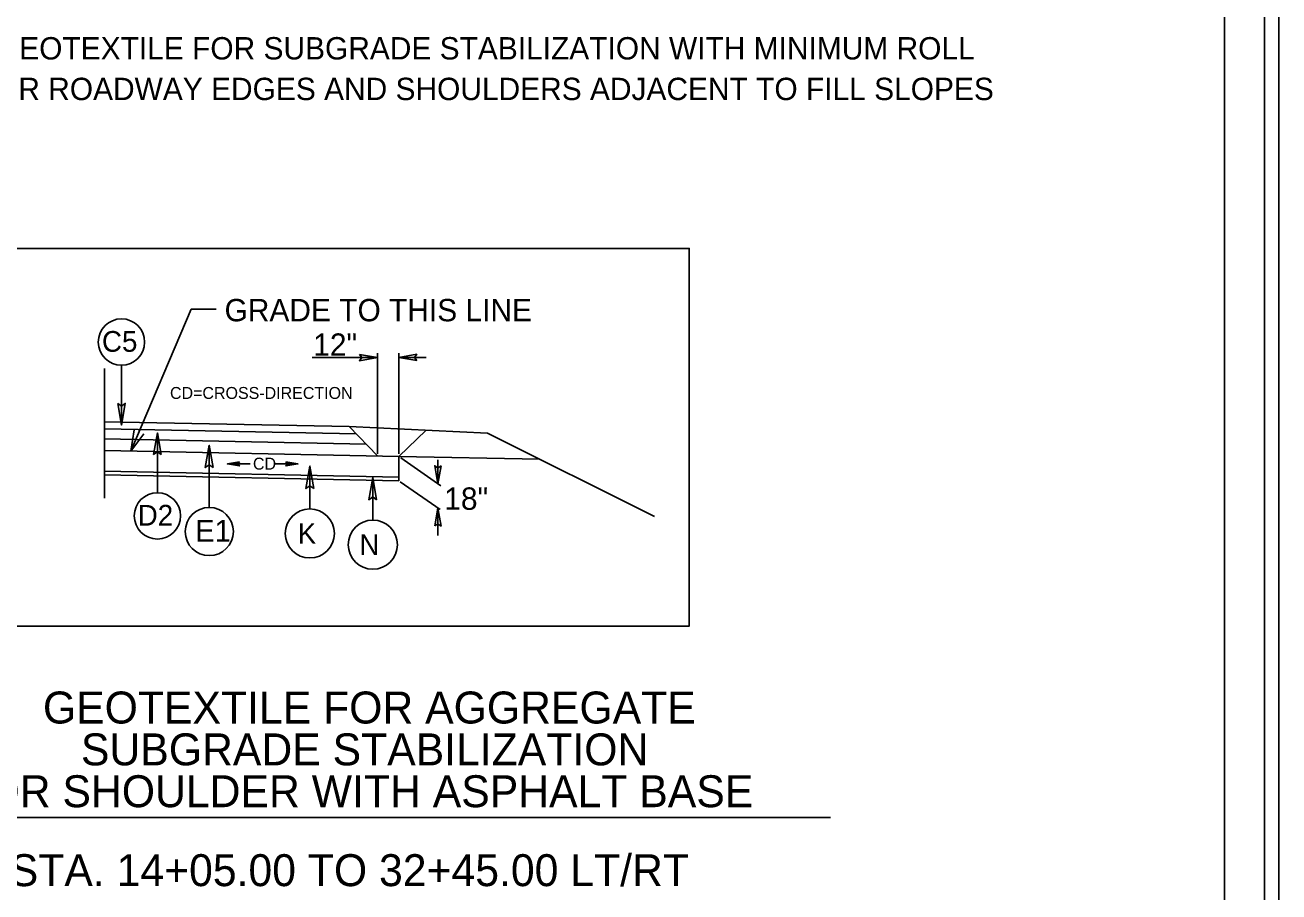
# Model space of a CAD drawing. Extents: x 1901718 to 1902220, y 193828 to 194187.
# Drawn here: x 1902095 to 1902134.24, y 194075.18 to 194102.32 of the extents above; entities that cross this region are included whole.
import ezdxf

# ---------------------------------------------------------------- set-up
doc = ezdxf.new("R2010")
doc.units = 0
for name, color, linetype in [('Old_Level_1', 7, 'Continuous'), ('Old_Level_11', 7, 'Continuous'), ('Old_Level_20', 7, 'Continuous'), ('Prop Dimension', 7, 'Continuous'), ('Prop Dimension Text', 7, 'Continuous'), ('Prop Lane Arrow CELL', 7, 'Continuous'), ('Prop Terminator CELL', 7, 'Continuous'), ('Sheet Border Standard 30in CELL', 7, 'Continuous'), ('Sheet Plot Border Inside CELL', 7, 'Continuous'), ('Sheet Plot Border Outside CELL', 7, 'Continuous'), ('Typical Hinge Slope Interstate CELL', 7, 'Continuous'), ('Typical ID Circle CELL', 7, 'Continuous'), ('Typical Pavement Slope CELL', 7, 'Continuous'), ('Typical Shoulder Slope CELL', 7, 'Continuous'), ('Typical Text General CELL', 7, 'Continuous'), ('Typical Text ID Circle CELL', 7, 'Continuous')]:
    doc.layers.add(name, color=color, linetype=linetype)

msp = doc.modelspace()

# ---------------------------------------------------------------- linework, layer by layer
at = {"layer": 'Old_Level_1'}
msp.add_lwpolyline([(1902098.718, 194089.524), (1902098.312, 194088.983), (1902098.415, 194089.651)], dxfattribs=at)
at = {"layer": 'Old_Level_11'}
for p, q in [((1902098.017, 194091.673), (1902098.017, 194089.799)), ((1902099.14, 194087.677), (1902099.14, 194089.552)), ((1902100.765, 194087.218), (1902100.765, 194089.167)), ((1902100.765, 194087.218), (1902100.765, 194089.167)), ((1902092.269, 194077.506), (1902120.212, 194077.506))]:
    msp.add_line(p, q, dxfattribs=at)
for points in [[(1902094.49, 194095.33), (1902115.785, 194095.33), (1902115.785, 194083.502), (1902094.49, 194083.502)], [(1902097.902, 194090.471), (1902098.017, 194089.799), (1902098.137, 194090.474), (1902098.017, 194090.388)], [(1902099.255, 194088.88), (1902099.14, 194089.552), (1902099.02, 194088.876), (1902099.14, 194088.962)], [(1902100.885, 194088.468), (1902100.765, 194089.167), (1902100.641, 194088.465), (1902100.765, 194088.554)], [(1902104.033, 194087.814), (1902103.913, 194088.512), (1902103.789, 194087.81), (1902103.913, 194087.899)], [(1902106.002, 194087.46), (1902105.882, 194088.158), (1902105.758, 194087.456), (1902105.882, 194087.545)]]:
    msp.add_lwpolyline(points, close=True, dxfattribs=at)
for centre, radius in [((1902098.017, 194092.398), 0.725), ((1902099.14, 194086.952), 0.725), ((1902100.765, 194086.463), 0.754), ((1902100.765, 194086.463), 0.754)]:
    msp.add_circle(centre, radius, dxfattribs=at)
at = {"layer": 'Prop Dimension'}
for p, q in [((1902100.197, 194093.429), (1902098.312, 194088.983)), ((1902100.197, 194093.429), (1902100.985, 194093.429)), ((1902097.484, 194087.511), (1902097.484, 194091.57)), ((1902102.042, 194088.583), (1902101.331, 194088.583)), ((1902102.829, 194088.583), (1902103.539, 194088.583))]:
    msp.add_line(p, q, dxfattribs=at)
at = {"layer": 'Prop Dimension Text'}
for p, q in [((1902103.983, 194091.911), (1902106.03, 194091.911)), ((1902106.03, 194088.894), (1902106.03, 194092.045)), ((1902106.696, 194088.894), (1902106.696, 194092.045)), ((1902106.696, 194091.911), (1902107.554, 194091.911)), ((1902106.758, 194088.771), (1902108.01, 194087.895)), ((1902107.921, 194087.957), (1902107.921, 194088.711)), ((1902106.743, 194088.022), (1902107.991, 194087.148)), ((1902107.919, 194086.343), (1902107.919, 194087.198))]:
    msp.add_line(p, q, dxfattribs=at)
at = {"layer": 'Prop Terminator CELL'}
for points in [[(1902105.468, 194092.006), (1902106.03, 194091.911), (1902105.466, 194091.809), (1902105.537, 194091.909)], [(1902107.257, 194091.816), (1902106.696, 194091.911), (1902107.26, 194092.012), (1902107.189, 194091.912)], [(1902101.706, 194088.648), (1902101.331, 194088.583), (1902101.708, 194088.517), (1902101.66, 194088.583)], [(1902103.165, 194088.648), (1902103.539, 194088.583), (1902103.163, 194088.517), (1902103.21, 194088.583)], [(1902108.018, 194088.518), (1902107.921, 194087.957), (1902107.821, 194088.522), (1902107.921, 194088.45)], [(1902107.822, 194086.637), (1902107.919, 194087.198), (1902108.019, 194086.634), (1902107.919, 194086.705)]]:
    msp.add_lwpolyline(points, close=True, dxfattribs=at)
at = {"layer": 'Sheet Border Standard 30in CELL'}
msp.add_lwpolyline([(1902132.544, 194155.514), (1901982.544, 194155.514), (1901982.544, 194050.514), (1902132.544, 194050.514)], close=True, dxfattribs=at)
at = {"layer": 'Sheet Plot Border Inside CELL'}
msp.add_lwpolyline([(1902133.794, 194155.769), (1901967.144, 194155.769), (1901967.144, 194050.259), (1902133.794, 194050.259)], close=True, dxfattribs=at)
at = {"layer": 'Sheet Plot Border Outside CELL'}
msp.add_lwpolyline([(1902134.244, 194158.014), (1901965.844, 194158.014), (1901965.844, 194048.014), (1902134.244, 194048.014)], close=True, dxfattribs=at)
at = {"layer": 'Typical Hinge Slope Interstate CELL'}
msp.add_line((1902109.472, 194089.548), (1902114.698, 194086.935), dxfattribs=at)
msp.add_lwpolyline([(1902097.487, 194088.354), (1902106.698, 194088.17), (1902106.696, 194088.055), (1902097.484, 194088.239)], close=True, dxfattribs=at)
at = {"layer": 'Typical ID Circle CELL'}
for p, q in [((1902103.913, 194087.174), (1902103.913, 194088.512)), ((1902105.882, 194086.82), (1902105.882, 194088.158))]:
    msp.add_line(p, q, dxfattribs=at)
for centre in [(1902103.913, 194086.404), (1902105.882, 194086.051)]:
    msp.add_circle(centre, 0.769, dxfattribs=at)
at = {"layer": 'Typical Pavement Slope CELL'}
for p, q in [((1902105.148, 194089.747), (1902097.484, 194089.9)), ((1902105.676, 194089.197), (1902097.474, 194089.361)), ((1902105.364, 194089.523), (1902097.48, 194089.68)), ((1902106.696, 194088.815), (1902097.484, 194089)), ((1902106.698, 194088.17), (1902097.487, 194088.354))]:
    msp.add_line(p, q, dxfattribs=at)
at = {"layer": 'Typical Shoulder Slope CELL'}
for p, q in [((1902105.148, 194089.747), (1902109.472, 194089.548)), ((1902106.03, 194088.829), (1902105.148, 194089.747)), ((1902107.55, 194089.636), (1902106.696, 194088.815)), ((1902106.696, 194088.815), (1902106.696, 194088.17)), ((1902106.696, 194088.815), (1902111.113, 194088.727)), ((1902106.696, 194088.055), (1902097.484, 194088.239))]:
    msp.add_line(p, q, dxfattribs=at)

# ---------------------------------------------------------------- texts
at = {"layer": 'Old_Level_20'}
for s, height, p in [('C5', 0.6491, (1902097.406, 194092.092)), ('D2', 0.6491, (1902098.525, 194086.649)), ('E1', 0.6822, (1902100.324, 194086.145)), ('E1', 0.6822, (1902100.324, 194086.145))]:
    msp.add_text(s, height=height, dxfattribs=at).set_placement(p)
at = {"layer": 'Prop Dimension Text'}
for s, p in [('*INSTALL GEOTEXTILE FOR SUBGRADE STABILIZATION WITH MINIMUM ROLL', (1902089.666, 194101.245)), ('WIDTH UNDER ROADWAY EDGES AND SHOULDERS ADJACENT TO FILL SLOPES', (1902088.808, 194099.973))]:
    msp.add_text(s, height=0.7, rotation=360, dxfattribs=at).set_placement(p)
for s, p in [('12"', (1902104.018, 194091.966)), ('18"', (1902108.12, 194087.144))]:
    msp.add_text(s, height=0.7, dxfattribs=at).set_placement(p)
at = {"layer": 'Prop Lane Arrow CELL'}
msp.add_text('-L- STA. 14+05.00 TO 32+45.00 LT/RT', height=0.99999, dxfattribs=at).set_placement((1902092.514, 194075.359))
at = {"layer": 'Typical Hinge Slope Interstate CELL'}
for s, height, p in [('CD=CROSS-DIRECTION', 0.37433, (1902099.535, 194090.615)), ('CD', 0.3743, (1902102.132, 194088.402))]:
    msp.add_text(s, height=height, dxfattribs=at).set_placement(p)
at = {"layer": 'Typical Text General CELL'}
for s, height, p in [('GRADE TO THIS LINE', 0.7, (1902101.243, 194093.046)), ('GEOTEXTILE FOR AGGREGATE ', 0.99999, (1902095.558, 194080.452)), ('SUBGRADE STABILIZATION ', 0.99999, (1902096.748, 194079.142)), ('FOR SHOULDER WITH ASPHALT BASE', 0.99999, (1902092.975, 194077.831))]:
    msp.add_text(s, height=height, dxfattribs=at).set_placement(p)
at = {"layer": 'Typical Text ID Circle CELL'}
for s, p in [('K', (1902103.537, 194086.084)), ('N', (1902105.468, 194085.731))]:
    msp.add_text(s, height=0.64, dxfattribs=at).set_placement(p)

doc.saveas('drawing.dxf')
